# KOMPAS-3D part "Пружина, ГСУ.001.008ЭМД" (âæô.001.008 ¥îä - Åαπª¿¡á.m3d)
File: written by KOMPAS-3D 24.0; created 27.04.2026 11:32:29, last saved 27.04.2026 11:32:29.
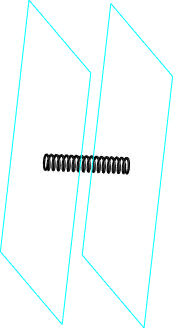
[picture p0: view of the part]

Document properties: Автор: USG_411; Полное имя файла: C:\Users\USG_411\Desktop\ГМ2704_411-15\Двигатель мясорубки\ГСУ.001.008 ЭМД - Пружина.m3d

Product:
- Part/product: Пружина  | designation ГСУ.001.008ЭМД
    Масса: 0.000086

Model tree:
1. Спираль рабочих витков
     Шаг = 0.99375; Диаметр 2 = 10
2. Сечение проволоки  (labels: Смещенная плоскость 1)
     Толщина стенки 1 = 0.01; Толщина стенки 2 = 0.01; Длина траектории = 146.634; Шаг = 0.3; Диаметр 2 = 10; Шаг = 0.3; Диаметр 2 = 10; Толщина стенки 1 = 0.01; Толщина стенки 2 = 0.01; Длина траектории = 6.83667
3. Сечение проволоки 2
     Толщина стенки 1 = 0.01; Толщина стенки 2 = 0.01; Длина траектории = 6.83667
4. Секущая плоскость 1  (labels: Сечение плоскостью 1)
5. Секущая плоскость 2  (labels: Сечение плоскостью 2)
6. Плоскость для сопряжений 1
7. Плоскость для сопряжений 2
8. Пружина
9. Эскиз:3

Expressions: L-(d+2*n2*d-2*n3*d); 0.5*d+(n2*d-n3*d); L-(d+2*n2*d-2*n3*d)+0.5*d+(n2*d-n3*d); (D1-d)/2
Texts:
  ГСУ.001.008
  ГСУ.001.008 ЭМД
  Расстояние от центра до окружности
  Направление навивки (1 - правое; 0 - левое)
  Наружный диаметр пружины, мм
  Диаметр проволоки, мм
  Число рабочих витков
  Число поджатых витков с одной стороны
  Число обработанных витков с одной стороны
  L0 - длина пружины в свободном состоянии, мм
  Кинематическая операция для рабочих витков
  Спираль первого поджатого витка
  Спираль второго поджатого витка
  Кинематическая операция для первого поджатого витка
  Кинематическая операция для второго поджатого витка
